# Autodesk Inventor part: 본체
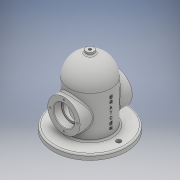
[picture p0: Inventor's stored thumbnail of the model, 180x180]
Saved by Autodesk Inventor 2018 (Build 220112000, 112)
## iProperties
Created: 2019-11
Part Number: 본체
Material: 일반
Document SubType Name: Modeling
Designer: USER
Density: 1 g/cm^3
Appearance: 기본값
Author: USER
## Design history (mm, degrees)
sketch "스케치1"
  geometry: C1 r 70 at (0, 0); 1 further point
  constraints: 1 centre point, 1 coincident
  dimensions: "d0" = 140 diameter of C1
extrude "돌출1" new body sketch "스케치1" distance "d1" = 10; taper "d2" = 0 deg
sketch "스케치4"
  geometry: C1 r 40 at (0, 0); 1 further point
  constraints: 1 centre point, 1 coincident
  dimensions: "d5" = 80 diameter of C1
extrude "돌출2" join sketch "스케치4" distance "d6" = 80; taper "d7" = 0 deg
sketch "스케치5"
  geometry: L1 (40, 90)-(-40, 90) reference; L2 (0, 130)-(0, 0); L3 (-40, 90)-(0, 90); L4 (0, 130)-(0, 90); A1 r 40 centre (0, 90) between (0, 130) and (-40, 90)
  constraints: 8 end point, 2 perpendicular, 2 point on circle, 1 centre point, 1 midpoint, 1 vertical
revolve "회전1" sketch "스케치5" stored, may be unused: angle "d9" = 90 deg
node "작업 평면1"
sketch "스케치7"
  geometry: L1 (-70, 0)-(70, 0) reference; C1 r 31 at (0, 50); 2 further points
  constraints: 1 centre point, 1 midpoint, 1 vertical alignment
  dimensions: "d11" = 62 diameter of C1; "d12" = 50 distance from line of L1 C1.centre
extrude "돌출3" join sketch "스케치7" stored distance "d13" = 50; taper "d14" = 0 deg
sketch "스케치8"
  geometry: C1 r 31 at (0, 0) reference; C2 r 20 at (0, 0); 1 further point
  constraints: 1 centre point, 1 coincident
  dimensions: "d15" = 40 diameter of C2
extrude "돌출4" cut sketch "스케치8" distance "d16" = 15; taper "d17" = 0 deg
sketch "스케치9"
  geometry: C1 r 20 at (0, 0) reference; C2 r 16.5 at (0, 0); 1 further point
  constraints: 1 centre point, 1 coincident
  dimensions: "d18" = 33 diameter of C2
extrude "돌출5" cut sketch "스케치9" extent not by distance; stored distance "d19" = 15; taper "d20" = 0 deg
sketch "스케치13"
  geometry: C1 r 30 at (0, 0); 1 further point
  constraints: 1 centre point, 1 coincident
  dimensions: "d21" = 60 diameter of C1
extrude "돌출6" cut sketch "스케치13" distance "d22" = 90; taper "d23" = 0 deg
sketch "스케치14"
  geometry: L1 (0, 0)-(0, 140.501); L2 (30, 90)-(-30, 90) reference; L3 (-30, 90)-(0, 90); L4 (0, 90)-(0, 120); A1 r 30 centre (0, 90) between (0, 120) and (-30, 90)
  constraints: 7 end point, 3 point on circle, 2 point on line, 1 centre point, 1 collinear, 1 midpoint, 1 perpendicular, 1 vertical
revolve "회전2" sketch "스케치14" stored, may be unused: angle "d24" = 90 deg
node "작업 평면3"
sketch "스케치16"
  geometry: C1 r 40 at (0, 0) reference; C2 r 7.5 at (0, 0); 1 further point
  constraints: 1 centre point, 1 coincident
  dimensions: "d27" = 15 diameter of C2
extrude "돌출7" join sketch "스케치16" stored distance "d28" = 5; taper "d29" = 0 deg
sketch "스케치18"
  geometry: 2 further points
  constraints: 1 coincident
hole "구멍1" sketch "스케치18" at (0, 0) diameter "d30" = 5.188; stored, may be unused: countersink angle "d34" = 90 deg, drill point angle "d36" = 118 deg; dims "d31" = 40, "d32" = 4, "d33" = 2, "d35" = 42
sketch "스케치19" dims "d37" = 52
  geometry: C1 r 16.5 at (0, 0) reference; 3 further points
  constraints: 2 vertical alignment, 1 coincident, 2 other
hole "구멍2" sketch "스케치19" at (0, 26) diameter "d38" = 3.242; stored, may be unused: countersink angle "d42" = 90 deg, drill point angle "d44" = 118 deg; dims "d39" = 8, "d40" = 4, "d41" = 2, "d43" = 10
node "작업 평면4"
sketch "스케치20"
  geometry: L1 (-70, -10)-(70, -10) reference; 3 further points
  constraints: 1 midpoint, 1 vertical alignment, 1 other
  dimensions: "d48" = 50 distance from line of L1 point (0, 40)
extrude "돌출8" join sketch "스케치20" distance "d49" = 0.5; taper "d50" = 0 deg
sketch "스케치22" dims "d52" = 110
  geometry: C1 r 4.5 at (-55, 0); 2 further points
  constraints: 2 horizontal alignment, 1 centre point, 1 coincident, 2 other
  dimensions: "d54" = 9 diameter of C1
extrude "돌출9" cut sketch "스케치22" distance "d55" = 15; taper "d56" = 0 deg
fillet "모깎기2" dims "d57" = 3
chamfer "모따기1" distance "d58" = 1; stored, may be unused: second distance "d59" = 2, angle "d60" = 45 deg
fillet "모깎기3" dims "d61" = 0.3
node "솔리드1"
mirror "미러1"
mirror "미러2"
pattern_circular "원형 패턴1" dims angle "d46" = 360 deg
mirror "미러3"
mirror "미러4"
node "투영된 루프1"
other parameters: "d26" = 135
